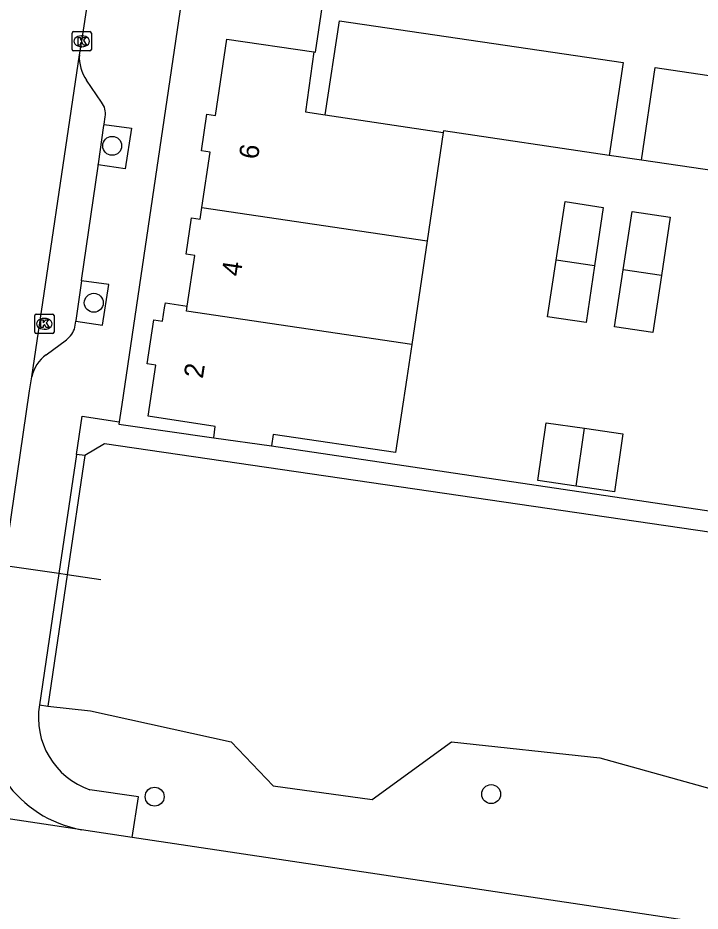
# Model space of a CAD drawing. Extents: x 164150 to 165261, y 382513 to 383432.
# Drawn here: x 164268.93 to 164304.16, y 382881.72 to 382927.81 of the extents above; entities that cross this region are included whole.
import ezdxf

# ---------------------------------------------------------------- set-up
doc = ezdxf.new("R2010")
doc.units = 0
for name, color, linetype in [('IMGEO_Boom', 7, 'Continuous'), ('IMGEO_Duiker', 7, 'Continuous'), ('IMGEO_Greppel_droge_sloot', 7, 'Continuous'), ('IMGEO_Groenvoorziening', 7, 'Continuous'), ('IMGEO_Kolk', 7, 'Continuous'), ('IMGEO_Muur', 7, 'Continuous'), ('IMGEO_Pand', 7, 'Continuous'), ('IMGEO_Pand_nummerreeks', 7, 'Continuous'), ('IMGEO_Parkeervlak_open', 7, 'Continuous'), ('IMGEO_Rijbaan_lokaal_gesloten', 7, 'Continuous'), ('IMGEO_Rijbaan_lokaal_open', 7, 'Continuous'), ('IMGEO_Voetpad_open', 7, 'Continuous')]:
    doc.layers.add(name, color=color, linetype=linetype)

msp = doc.modelspace()

# ---------------------------------------------------------------- linework, layer by layer
at = {"layer": 'IMGEO_Boom'}
for centre in [(164273.798, 382921.209), (164272.847, 382913.108), (164293.369, 382887.754), (164275.989, 382887.622)]:
    msp.add_circle(centre, 0.489, dxfattribs=at)
at = {"layer": 'IMGEO_Duiker'}
msp.add_lwpolyline([(164273.212, 382898.819), (164271.474, 382899.069), (164271.046, 382899.131), (164260.536, 382900.643), (164260.114, 382900.704), (164258.36, 382900.956)], dxfattribs=at)
at = {"layer": 'IMGEO_Greppel_droge_sloot'}
for points in [[(164322.576, 382897.741), (164319.951, 382899.035), (164273.404, 382905.823), (164272.384, 382905.231)], [(164270.473, 382892.294), (164272.677, 382892.051), (164279.942, 382890.457), (164282.11, 382888.183), (164287.223, 382887.472), (164291.315, 382890.454), (164298.989, 382889.623), (164312.776, 382885.789), (164315.288, 382884.411), (164318.145, 382883.434), (164320.656, 382884.826)]]:
    msp.add_lwpolyline(points, dxfattribs=at)
at = {"layer": 'IMGEO_Groenvoorziening'}
for points in [[(164274.157, 382906.967), (164274.138, 382906.837), (164279.041, 382906.142)], [(164282.019, 382905.72), (164313.431, 382901.058)]]:
    msp.add_lwpolyline(points, dxfattribs=at)
at = {"layer": 'IMGEO_Kolk'}
for p, q in [((164271.724, 382926.178), (164271.724, 382927.03)), ((164271.799, 382927.104), (164272.651, 382927.104)), ((164272.212, 382926.884), (164272.237, 382926.884)), ((164272.725, 382927.03), (164272.725, 382926.178)), ((164272.651, 382926.104), (164271.799, 382926.104)), ((164272.235, 382926.324), (164272.21, 382926.324)), ((164269.795, 382911.6), (164269.795, 382912.452)), ((164269.87, 382912.526), (164270.722, 382912.526)), ((164270.283, 382912.306), (164270.308, 382912.306)), ((164270.796, 382912.452), (164270.796, 382911.6)), ((164270.306, 382911.746), (164270.281, 382911.746)), ((164270.722, 382911.526), (164269.87, 382911.526))]:
    msp.add_line(p, q, dxfattribs=at)
for points in [[(164271.724, 382926.178), (164271.724, 382927.03)], [(164271.799, 382927.104), (164272.651, 382927.104)], [(164272.725, 382927.03), (164272.725, 382926.178)], [(164272.045, 382926.804), (164272.168, 382926.804), (164272.168, 382926.653), (164272.298, 382926.804), (164272.462, 382926.804), (164272.316, 382926.653), (164272.469, 382926.404), (164272.317, 382926.404), (164272.232, 382926.568), (164272.168, 382926.501), (164272.168, 382926.404), (164272.045, 382926.404), (164272.045, 382926.804)], [(164272.651, 382926.104), (164271.799, 382926.104)], [(164269.795, 382911.6), (164269.795, 382912.452)], [(164269.87, 382912.526), (164270.722, 382912.526)], [(164270.116, 382912.226), (164270.239, 382912.226), (164270.239, 382912.075), (164270.369, 382912.226), (164270.533, 382912.226), (164270.387, 382912.075), (164270.54, 382911.826), (164270.388, 382911.826), (164270.303, 382911.99), (164270.239, 382911.923), (164270.239, 382911.826), (164270.116, 382911.826), (164270.116, 382912.226)], [(164270.796, 382912.452), (164270.796, 382911.6)], [(164270.722, 382911.526), (164269.87, 382911.526)]]:
    msp.add_lwpolyline(points, dxfattribs=at)
for centre, start, end in [((164271.801, 382927.028), 91.552, 178.448), ((164271.801, 382927.028), 91.552, 178.448), ((164272.649, 382927.028), 1.552, 88.448), ((164272.649, 382927.028), 1.552, 88.448), ((164271.801, 382926.18), 181.552, 268.448), ((164271.801, 382926.18), 181.552, 268.448), ((164272.649, 382926.18), 271.552, 358.448), ((164272.649, 382926.18), 271.552, 358.448), ((164269.872, 382912.45), 91.552, 178.448), ((164269.872, 382912.45), 91.552, 178.448), ((164270.72, 382912.45), 1.552, 88.448), ((164270.72, 382912.45), 1.552, 88.448), ((164269.872, 382911.602), 181.552, 268.448), ((164269.872, 382911.602), 181.552, 268.448), ((164270.72, 382911.602), 271.552, 358.448), ((164270.72, 382911.602), 271.552, 358.448)]:
    msp.add_arc(centre, 0.0765, start, end, dxfattribs=at)
for centre, major_axis, ratio, start_param, end_param in [((164272.211, 382926.604), (-0.387, 0.002), 0.722429, 4.712389, 7.853982), ((164272.236, 382926.604), (-0.39, 0.002), 0.717154, 1.570796, 4.712389), ((164270.282, 382912.026), (-0.387, 0.002), 0.722429, 4.712389, 7.853982), ((164270.307, 382912.026), (-0.39, 0.002), 0.717154, 1.570796, 4.712389)]:
    msp.add_ellipse(centre, major_axis=major_axis, ratio=ratio, start_param=start_param, end_param=end_param, dxfattribs=at)
at = {"layer": 'IMGEO_Muur'}
for points in [[(164271.959, 382905.274), (164271.046, 382899.131), (164270.039, 382892.36)], [(164272.384, 382905.231), (164271.474, 382899.069), (164270.473, 382892.294)], [(164272.384, 382905.231), (164271.959, 382905.274)], [(164270.039, 382892.36), (164270.473, 382892.294)]]:
    msp.add_lwpolyline(points, dxfattribs=at)
at = {"layer": 'IMGEO_Pand'}
for points in [[(164278.43, 382918.021), (164278.854, 382920.889), (164278.404, 382920.956), (164278.682, 382922.835), (164279.133, 382922.769), (164279.717, 382926.721), (164284.213, 382926.053)], [(164284.213, 382926.053), (164283.782, 382922.964), (164284.795, 382922.813)], [(164284.795, 382922.813), (164290.895, 382921.902)], [(164290.895, 382921.902), (164290.064, 382916.301)], [(164296.727, 382915.316), (164297.186, 382918.331), (164299.147, 382918.034), (164298.703, 382915.023)], [(164277.678, 382912.941), (164278.065, 382915.552), (164277.615, 382915.619), (164277.893, 382917.498), (164278.343, 382917.432), (164278.43, 382918.021)], [(164278.43, 382918.021), (164290.064, 382916.301)], [(164300.186, 382914.804), (164300.644, 382917.823), (164302.62, 382917.519), (164302.164, 382914.512)], [(164290.064, 382916.301), (164289.272, 382910.96)], [(164298.703, 382915.023), (164298.271, 382912.091), (164296.28, 382912.384), (164296.727, 382915.316)], [(164298.703, 382915.023), (164296.727, 382915.316)], [(164302.164, 382914.512), (164301.72, 382911.577), (164299.742, 382911.876), (164300.186, 382914.804)], [(164302.164, 382914.512), (164300.186, 382914.804)], [(164279.041, 382906.142), (164279.123, 382906.733), (164275.66, 382907.259), (164276.058, 382909.886), (164275.608, 382909.954), (164275.952, 382912.228), (164276.402, 382912.16), (164276.507, 382912.848), (164276.545, 382913.1), (164277.678, 382912.941)], [(164289.272, 382910.96), (164277.639, 382912.68), (164277.678, 382912.941)], [(164289.272, 382910.96), (164289.017, 382909.243), (164288.433, 382905.376), (164282.11, 382906.314), (164282.019, 382905.72)], [(164297.766, 382903.646), (164295.787, 382903.94), (164296.209, 382906.915), (164298.19, 382906.634)], [(164298.19, 382906.634), (164300.17, 382906.353), (164299.744, 382903.352), (164297.766, 382903.646)], [(164297.766, 382903.646), (164298.19, 382906.634)], [(164279.041, 382906.142), (164282.019, 382905.72)]]:
    msp.add_lwpolyline(points, dxfattribs=at)
at = {"layer": 'IMGEO_Parkeervlak_open'}
for points in [[(164273.082, 382920.233), (164273.089, 382920.282), (164273.374, 382922.257), (164273.381, 382922.305)], [(164299.469, 382920.718), (164290.906, 382921.976), (164290.895, 382921.902)], [(164312.03, 382918.763), (164312.046, 382918.869), (164301.137, 382920.472)], [(164272.218, 382914.239), (164271.922, 382912.188), (164271.919, 382912.165)]]:
    msp.add_lwpolyline(points, dxfattribs=at)
at = {"layer": 'IMGEO_Rijbaan_lokaal_gesloten'}
for points in [[(164272.211, 382885.919), (164255.48, 382888.431)], [(164274.826, 382885.521), (164272.211, 382885.919)], [(164314.585, 382879.574), (164314.161, 382879.638), (164274.826, 382885.521)]]:
    msp.add_lwpolyline(points, dxfattribs=at)
at = {"layer": 'IMGEO_Rijbaan_lokaal_open'}
for points in [[(164284.213, 382926.053), (164284.289, 382926.042), (164284.757, 382929.176), (164277.599, 382930.234)], [(164272.102, 382925.91), (164272.225, 382926.604), (164272.552, 382928.781)], [(164284.795, 382922.813), (164285.538, 382927.658), (164300.186, 382925.513), (164299.469, 382920.718)], [(164269.642, 382909.28), (164272.102, 382925.91)], [(164301.137, 382920.472), (164301.836, 382925.251), (164316.467, 382923.089), (164315.762, 382918.213)], [(164301.137, 382920.472), (164299.469, 382920.718)], [(164267.326, 382893.52), (164269.536, 382908.558), (164269.642, 382909.28)]]:
    msp.add_lwpolyline(points, dxfattribs=at)
msp.add_arc((164273.301, 382891.961), 6.139, 171.6262, 259.7736, dxfattribs=at)
at = {"layer": 'IMGEO_Voetpad_open'}
for points in [[(164277.599, 382930.234), (164274.29, 382907.865), (164274.157, 382906.967)], [(164273.246, 382923.455), (164272.479, 382924.595)], [(164273.381, 382922.305), (164273.384, 382922.322), (164273.44, 382922.713)], [(164273.381, 382922.305), (164274.787, 382922.12), (164274.466, 382920.029), (164273.082, 382920.233)], [(164272.218, 382914.239), (164272.221, 382914.26), (164273.071, 382920.156), (164273.082, 382920.233)], [(164271.919, 382912.165), (164273.301, 382911.962), (164273.622, 382914.053), (164272.218, 382914.239)], [(164271.873, 382911.846), (164271.919, 382912.165)], [(164270.395, 382910.431), (164271.431, 382911.203)], [(164271.959, 382905.274), (164272.253, 382907.25), (164274.157, 382906.967)], [(164274.826, 382885.521), (164275.153, 382887.621), (164272.647, 382887.983)]]:
    msp.add_lwpolyline(points, dxfattribs=at)
for centre, radius, start, end in [((164274.166, 382925.79), 2.067, 176.6742, 215.3201), ((164272.518, 382922.868), 0.935, 350.4467, 38.8579), ((164270.744, 382912.148), 1.169, 305.9916, 344.999), ((164271.506, 382908.882), 1.906, 125.6609, 167.9526), ((164273.922, 382891.708), 3.937, 170.4654, 251.1111)]:
    msp.add_arc(centre, radius, start, end, dxfattribs=at)

# ---------------------------------------------------------------- texts
at = {"layer": 'IMGEO_Pand_nummerreeks'}
for s, rotation, p in [('6', 81.5892, (164281.32, 382920.476)), ('4', 81.5663, (164280.428, 382914.439)), ('2', 81.3829, (164278.477, 382909.17))]:
    msp.add_text(s, height=1, rotation=rotation, dxfattribs=at).set_placement(p)

doc.saveas('drawing.dxf')
